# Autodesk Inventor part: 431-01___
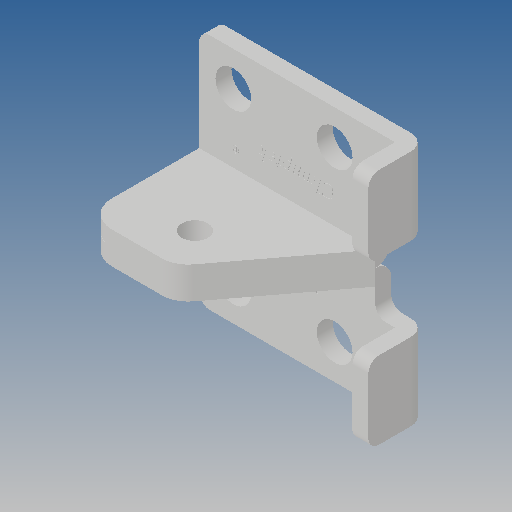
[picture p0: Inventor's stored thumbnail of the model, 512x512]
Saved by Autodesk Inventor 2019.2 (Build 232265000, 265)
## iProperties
Created: 2010-06
Part Number: 431-01___
Material: Ogólny
Document SubType Name: Modeling
Designer: CADENGINEERING4
Density: 1 g/cm^3
Appearance: Domyślna
Author: CADENGINEERING4
Revision Number: ANY
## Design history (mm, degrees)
feature "NONE"
feature "NONE:1"
node "Bryła1"
node "Bryła2"
